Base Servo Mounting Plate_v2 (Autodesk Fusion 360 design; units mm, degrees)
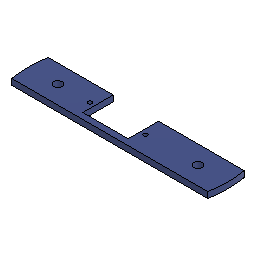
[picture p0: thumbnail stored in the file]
sketch "Sketch2" plane through (0, 0, 0) normal (0, 0, 1) x axis (1, 0, 0)
  line L1 (6.2, 6.1) -> (-16.5, 6.1)
  line L2 (-49.4157, -7.6217) -> (49.4157, 7.6217)
  line L3 (49.1649, 9.1) -> (-49.1649, 9.1)
  line L4 (6.2, 6.1) -> (-16.5, -6.1)
  line L5 (49.4157, -7.6217) -> (-49.4157, 7.6217)
  line L6 (6.2, -6.1) -> (6.2, 6.1)
  line L7 (-49.1649, -9.1) -> (49.1649, -9.1)
  line L8 (-16.5, 6.1) -> (-16.5, -6.1)
  line L9 (-16.5, -6.1) -> (6.2, -6.1)
  line L10 (-16.5, 6.1) -> (6.2, -6.1)
  line L11 (0, 9.1) -> (0, -9.1)
  line L12 (-5.15, -2.0049) -> (-5.15, 2.3846)
  line L13 (50, 0) -> (-50, 0)
  line L14 (-16.5, 9.1) -> (-16.5, 6.1)
  line L15 (6.2, 9.1) -> (6.2, 6.1)
  circle C1 centre (8.75, 0) radius 1
  circle C2 centre (35, 0) radius 2.1
  circle C3 centre (-19.05, 0) radius 1
  circle C4 centre (0, 0) radius 2.5
  circle C5 centre (-35, 0) radius 2.1
  arc A1 centre (0, 0) radius 50 clockwise from (-49.1649, -9.1) to (-49.1649, 9.1)
  arc A2 centre (0, 0) radius 50 clockwise from (49.1649, 9.1) to (49.1649, -9.1)
  arc A3 centre (0.2, 0) radius 50 clockwise from (-48.9649, -9.1) to (-48.9649, 9.1)
  arc A4 centre (-0.2, 0) radius 50 clockwise from (48.9649, 9.1) to (48.9649, -9.1)
  point P22 (-50, 0)
  point P21 (50, 0)
  point P19 (-19.05, 0)
  point P14 (8.75, 0)
  point P26 (-5.15, 0)
  point P30 (0, 0)
  point P12 (-49.4157, 7.6217)
  point P33 (-49.4157, -7.6217)
  point P29 (49.4157, -7.6217)
  point P28 (49.4157, 7.6217)
  point P32 (-19.05, 0)
  point P13 (35, 0)
  point P3 (0, -9.1)
  point P2 (0, 9.1)
  point P7 (-19.05, 0)
  point P8 (8.75, 0)
  point P5 (-19.05, 0)
  point P6 (8.75, 0)
  point P41 (-16.5, 9.1)
  point P9 (0, 0)
  point P17 (-16.5, 6.1)
  point P20 (6.2, 6.1)
  point P24 (-16.5, -6.1)
  concentric C4 A1
  coincident P22 A1
  coincident P21 A2
  horizontal L13
  coincident P19 L13
  coincident P14 L13
  perpendicular L12 L13
  horizontal L9
  perpendicular L8 L9
  parallel L1 L9
  parallel L6 L8
  coincident P26 L10
  coincident P26 L4
  coincident P26 L13
  coincident P26 L12
  horizontal L3
  parallel L3 L7
  coincident P30 L5
  coincident P30 L2
  coincident P12 A1
  coincident P33 A1
  coincident P29 A2
  coincident P28 A2
  coincident P19 P32
  coincident P13 L13
  midpoint P3 L7
  midpoint P2 L3
  symmetric C2 L11 C5
  coincident P7 P19
  coincident P8 P14
  coincident P5 P32
  coincident P6 P8
  concentric A1 A2
  coincident L3 P41
  perpendicular L3 L14
  perpendicular L3 L15
  dimension "d19" diameter C4 = 5
  dimension "d20" diameter C3 = 2
  dimension "d21" distance P9 P19 = 19.05
  dimension "d22" diameter C1 = 2 (= "d20")
  dimension "d23" distance P9 P14 = 8.75
  dimension "d24" distance P9 L12 = 5.15
  dimension "d25" distance P17 P20 = 22.7
  dimension "d26" distance P17 P24 = 12.2
  dimension "d28" diameter C2 = 4.2
  dimension "d29" distance P9 P13 = 35
extrude "Extrude2" new body sketch "Sketch2" profile of C1 C2 L3 L6 L7 C3 L8 L9 C5 A3 A4 L14 L15 along normal blind 3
